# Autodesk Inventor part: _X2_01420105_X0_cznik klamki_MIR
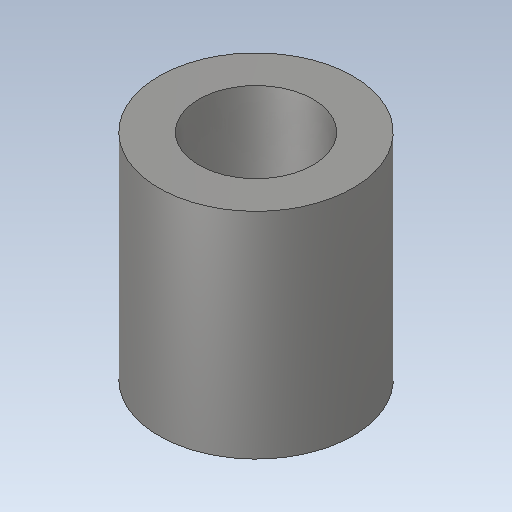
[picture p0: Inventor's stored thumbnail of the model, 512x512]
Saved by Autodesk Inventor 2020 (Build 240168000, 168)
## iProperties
Created: 2015-11
Part Number: _X2_01420105_X0_cznik klamki_MIR
Material: Ogólny
Document SubType Name: Modeling
Designer: Tomasz
Density: 1 g/cm^3
Appearance: Domyślna
Sending System: SolidWorks 2017
Last Author: Tomasz
Last Saved: 2017-10-01
Author: Tomasz
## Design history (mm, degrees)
feature "Imported1"
node "Bryła1"
